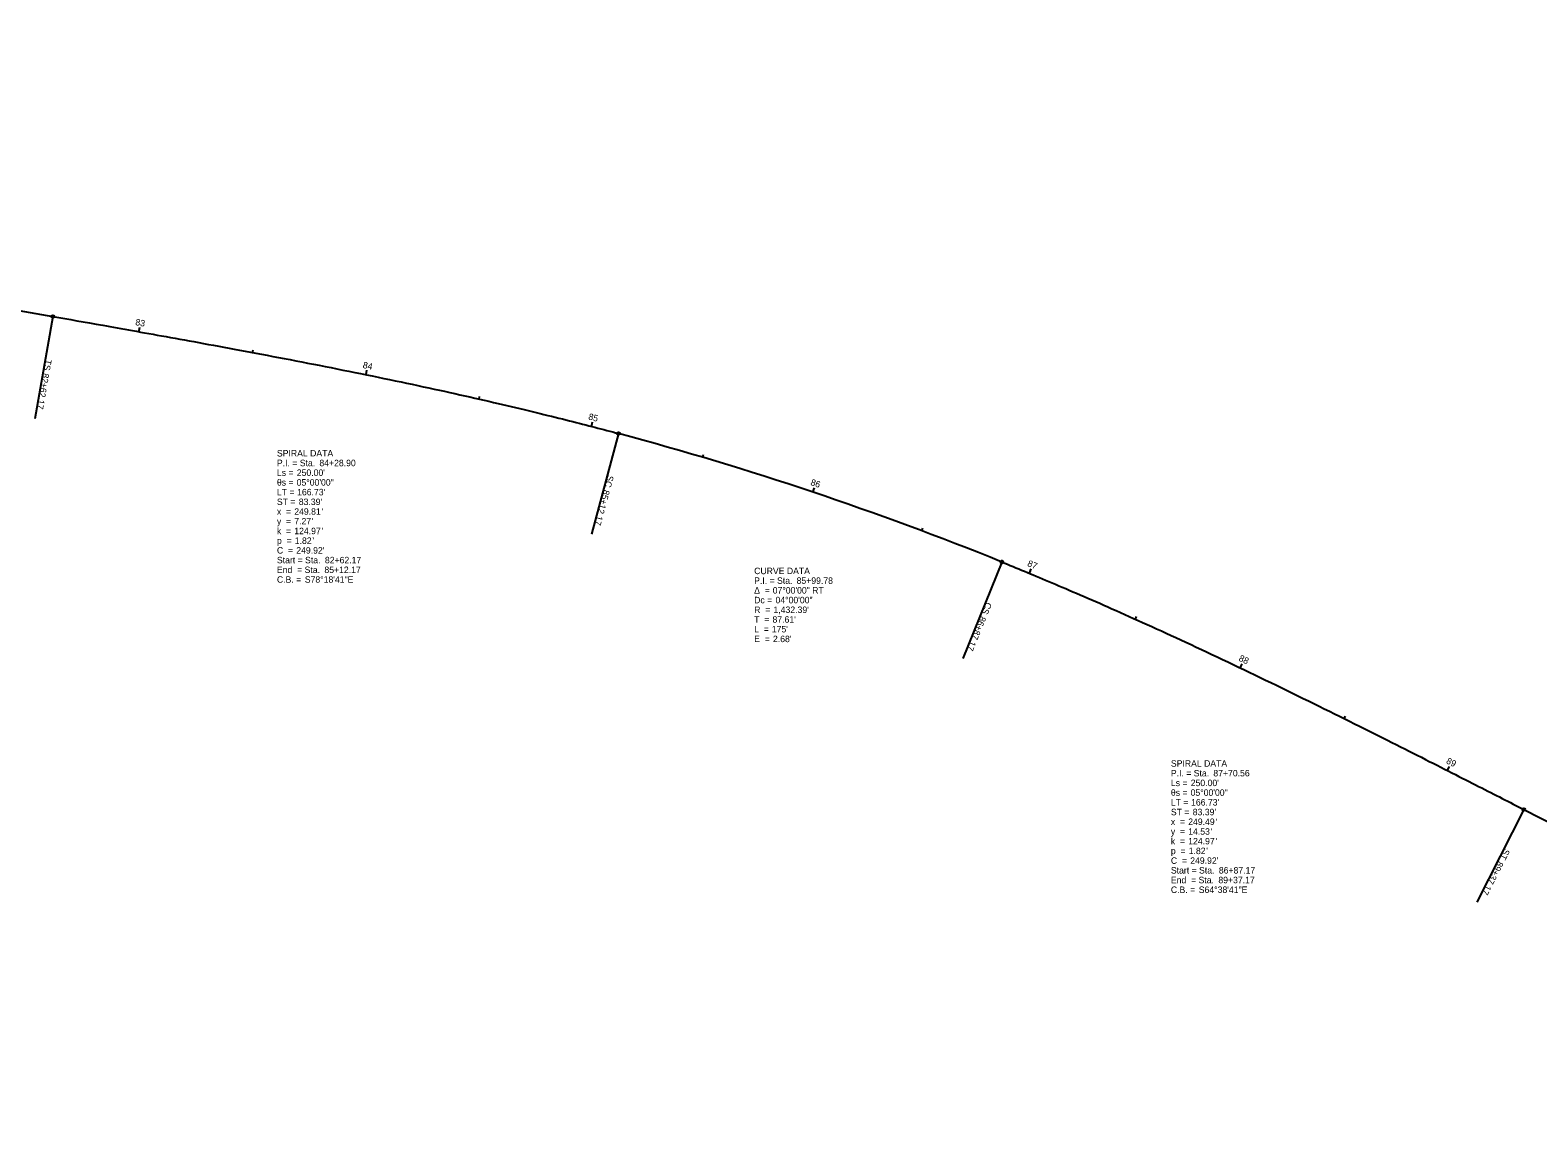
# Model space of a CAD drawing. Extents: x 1999336 to 2003366, y 252766 to 253936.
# Drawn here: x 2000958 to 2001610, y 252978 to 253453 of the extents above; entities that cross this region are included whole.
import ezdxf

# ---------------------------------------------------------------- set-up
doc = ezdxf.new("R2010")
doc.units = 0
for name, color, linetype in [('GE_X_CL_20', 7, 'Continuous'), ('GK_Visualization', 7, 'Continuous'), ('RW_X_Esmt_SH', 7, 'Continuous'), ('SC_Scratch3', 7, 'Continuous'), ('SV_X_Control_Cells_Found', 7, 'Continuous'), ('SV_X_Text_Elevation', 7, 'Continuous'), ('SV_X_Text_Name', 7, 'Continuous')]:
    doc.layers.add(name, color=color, linetype=linetype)

msp = doc.modelspace()

# ---------------------------------------------------------------- linework, layer by layer
at = {"layer": 'GE_X_CL_20'}
for p, q in [((2000967.83, 253329.36), (2000960, 253285.05)), ((2001005.08, 253322.76), (2001005.29, 253323.94)), ((2001103.34, 253304.18), (2001103.58, 253305.36)), ((2001200.8, 253281.84), (2001201.3, 253283.77)), ((2001212.56, 253278.73), (2001200.9, 253235.27)), ((2001296.64, 253253.38), (2001297.02, 253254.52)), ((2001378.39, 253223.18), (2001361.52, 253181.46)), ((2001390.27, 253218.31), (2001390.73, 253219.42)), ((2001481.5, 253177.4), (2001482.02, 253178.48)), ((2001571.11, 253133.02), (2001571.66, 253134.09)), ((2001604.23, 253116.16), (2001583.79, 253076.07))]:
    msp.add_line(p, q, dxfattribs=at)
for centre in [(2000967.83, 253329.36), (2001212.56, 253278.73), (2001378.39, 253223.18), (2001604.23, 253116.16)]:
    msp.add_circle(centre, 0.6, dxfattribs=at)
at = {"layer": 'GK_Visualization'}
for p, q in [((2000267.25, 253453.17), (2000967.83, 253329.36)), ((2001604.23, 253116.16), (2001875.85, 252977.63))]:
    msp.add_line(p, q, dxfattribs=at)
msp.add_arc((2000841.3, 251895.29), 1432.39, 67.97811, 74.97808, dxfattribs=at)
msp.add_arc((2000841.3, 251895.29), 1432.39, 67.97811, 74.97808, dxfattribs=at)
for points in [[(2000967.83, 253329.36), (2000974.67, 253328.16), (2000988.34, 253325.74), (2001015.69, 253320.87), (2001049.85, 253314.66), (2001090.78, 253306.82), (2001131.58, 253298.37), (2001165.44, 253290.68), (2001192.41, 253284.04), (2001205.85, 253280.53), (2001212.56, 253278.73)], [(2000967.83, 253329.36), (2000974.67, 253328.16), (2000988.34, 253325.74), (2001015.69, 253320.87), (2001049.85, 253314.66), (2001090.78, 253306.82), (2001131.58, 253298.37), (2001165.44, 253290.68), (2001192.41, 253284.04), (2001205.85, 253280.53), (2001212.56, 253278.73)], [(2001378.39, 253223.18), (2001384.83, 253220.57), (2001397.67, 253215.27), (2001423.2, 253204.33), (2001454.86, 253190.07), (2001492.51, 253172.23), (2001529.9, 253153.84), (2001560.91, 253138.21), (2001585.67, 253125.62), (2001598.05, 253119.31), (2001604.23, 253116.16)], [(2001378.39, 253223.18), (2001384.83, 253220.57), (2001397.67, 253215.27), (2001423.2, 253204.33), (2001454.86, 253190.07), (2001492.51, 253172.23), (2001529.9, 253153.84), (2001560.91, 253138.21), (2001585.67, 253125.62), (2001598.05, 253119.31), (2001604.23, 253116.16)]]:
    msp.add_open_spline(points, degree=3, dxfattribs=at)
at = {"layer": 'SC_Scratch3'}
for p, q in [((2000967.83, 253329.36), (2000960, 253285.05)), ((2001005.08, 253322.76), (2001005.43, 253324.72)), ((2001054.26, 253313.77), (2001054.49, 253314.95)), ((2001103.34, 253304.18), (2001103.74, 253306.14)), ((2001152.21, 253293.65), (2001152.48, 253294.82)), ((2001200.8, 253281.84), (2001201.3, 253283.77)), ((2001212.56, 253278.73), (2001200.9, 253235.27)), ((2001248.97, 253268.45), (2001249.31, 253269.6)), ((2001296.64, 253253.38), (2001297.28, 253255.28)), ((2001343.76, 253236.66), (2001344.18, 253237.79)), ((2001378.39, 253223.18), (2001361.52, 253181.46)), ((2001390.27, 253218.31), (2001391.03, 253220.16)), ((2001436.15, 253198.45), (2001436.64, 253199.55)), ((2001481.5, 253177.4), (2001482.36, 253179.2)), ((2001526.44, 253155.48), (2001526.98, 253156.56)), ((2001571.11, 253133.02), (2001572.02, 253134.8)), ((2001604.23, 253116.16), (2001583.79, 253076.07))]:
    msp.add_line(p, q, dxfattribs=at)
for centre in [(2000967.83, 253329.36), (2001212.56, 253278.73), (2001378.39, 253223.18), (2001604.23, 253116.16)]:
    msp.add_circle(centre, 0.6, dxfattribs=at)
at = {"layer": 'SV_X_Text_Name'}
for p, q in [((2000967.83, 253329.36), (2000960, 253285.05)), ((2001200.8, 253281.84), (2001201.1, 253283)), ((2001212.56, 253278.73), (2001200.9, 253235.27)), ((2001378.39, 253223.18), (2001361.52, 253181.46)), ((2001604.23, 253116.16), (2001583.79, 253076.07))]:
    msp.add_line(p, q, dxfattribs=at)
for centre in [(2000967.83, 253329.36), (2001212.56, 253278.73), (2001378.39, 253223.18), (2001604.23, 253116.16)]:
    msp.add_circle(centre, 0.6, dxfattribs=at)

# ---------------------------------------------------------------- texts
at = {"layer": 'GE_X_CL_20'}
for s, rotation, p in [('82+62.17', 259.97809, (2000963.57, 253304.98)), ('TS', 259.97809, (2000964.62, 253310.97)), ('85', 345.45294, (2001199.3, 253284.86)), ('SC', 254.97808, (2001207.82, 253260.9)), ('85+12.17', 254.97808, (2001206.13, 253254.6)), ('86+87.17', 247.97811, (2001369.07, 253200.01)), ('CS', 247.97811, (2001371.52, 253206.05)), ('ST', 242.97809, (2001595.79, 253099.5)), ('89+37.17', 242.97809, (2001593.03, 253094.08))]:
    msp.add_text(s, height=2.8, rotation=rotation, dxfattribs=at).set_placement(p)
at = {"layer": 'RW_X_Esmt_SH'}
for s, p in [('SPIRAL DATA', (2001064.78, 253268.81)), ('P.I. = Sta. ', (2001064.78, 253264.61)), ('84+28.90', (2001083.15, 253264.61)), ('θs = ', (2001064.78, 253256.21)), ('Ls = ', (2001064.78, 253260.41)), ('05°00\'00"', (2001073.31, 253256.21)), ("250.00'", (2001073.37, 253260.41)), ('LT = ', (2001064.78, 253252.01)), ("166.73'", (2001073.51, 253252.01)), ('x  = ', (2001064.78, 253243.61)), ('ST = ', (2001064.78, 253247.81)), ('249.81', (2001072.28, 253243.61)), ("83.39'", (2001074.24, 253247.81)), ("'", (2001084.24, 253243.61)), ('y  = ', (2001064.78, 253239.41)), ('7.27', (2001072.28, 253239.41)), ("'", (2001079.89, 253239.41)), ('p  = ', (2001064.78, 253231.01)), ('k  = ', (2001064.78, 253235.21)), ('124.97', (2001072.28, 253235.21)), ('1.82', (2001072.5, 253231.01)), ("'", (2001080.11, 253231.01)), ("'", (2001084.24, 253235.21)), ('C  = ', (2001064.78, 253226.81)), ("249.92'", (2001073.15, 253226.81)), ('Start = Sta. ', (2001064.78, 253222.61)), ('End  = Sta. ', (2001064.78, 253218.41)), ('85+12.17', (2001085.32, 253218.41)), ('82+62.17', (2001085.54, 253222.61)), ('CURVE DATA', (2001271.23, 253217.93)), ('C.B. = ', (2001064.78, 253214.21)), ('S78°18\'41"E', (2001076.84, 253214.21)), ('P.I. = Sta. ', (2001271.23, 253213.73)), ('85+99.78', (2001289.59, 253213.73)), ('Δ  = ', (2001271.23, 253209.53)), ('Dc = ', (2001271.23, 253205.33)), ('07°00\'00" RT', (2001279.25, 253209.53)), ('04°00\'00"', (2001280.46, 253205.33)), ('T  = ', (2001271.23, 253196.93)), ('R  = ', (2001271.23, 253201.13)), ("87.61'", (2001279.16, 253196.93)), ("1,432.39'", (2001279.59, 253201.13)), ('L  = ', (2001271.23, 253192.73)), ("175'", (2001278.87, 253192.73)), ('E  = ', (2001271.23, 253188.53)), ("2.68'", (2001279.38, 253188.53)), ('SPIRAL DATA', (2001451.5, 253134.66)), ('P.I. = Sta. ', (2001451.5, 253130.46)), ('Ls = ', (2001451.5, 253126.26)), ("250.00'", (2001460.09, 253126.26)), ('87+70.56', (2001469.87, 253130.46)), ('θs = ', (2001451.5, 253122.06)), ('05°00\'00"', (2001460.04, 253122.06)), ('ST = ', (2001451.5, 253113.66)), ('LT = ', (2001451.5, 253117.86)), ("166.73'", (2001460.23, 253117.86)), ("83.39'", (2001460.96, 253113.66)), ('x  = ', (2001451.5, 253109.46)), ('249.49', (2001459, 253109.46)), ("'", (2001470.96, 253109.46)), ('y  = ', (2001451.5, 253105.26)), ('k  = ', (2001451.5, 253101.06)), ('14.53', (2001459, 253105.26)), ('124.97', (2001459, 253101.06)), ("'", (2001468.79, 253105.26)), ("'", (2001470.96, 253101.06)), ('C  = ', (2001451.5, 253092.66)), ('p  = ', (2001451.5, 253096.86)), ('1.82', (2001459.22, 253096.86)), ("249.92'", (2001459.87, 253092.66)), ("'", (2001466.83, 253096.86)), ('Start = Sta. ', (2001451.5, 253088.46)), ('86+87.17', (2001472.26, 253088.46)), ('C.B. = ', (2001451.5, 253080.06)), ('End  = Sta. ', (2001451.5, 253084.26)), ('S64°38\'41"E', (2001463.57, 253080.06)), ('89+37.17', (2001472.05, 253084.26))]:
    msp.add_text(s, height=2.8, dxfattribs=at).set_placement(p)
at = {"layer": 'SC_Scratch3'}
for s, rotation, p in [('83', 349.86359, (2001003.38, 253325.65)), ('82+62.17', 259.97809, (2000963.57, 253304.98)), ('TS', 259.97809, (2000964.62, 253310.97)), ('84', 348.45827, (2001101.74, 253307.11)), ('85', 345.45294, (2001199.3, 253284.86)), ('SC', 254.97808, (2001207.82, 253260.9)), ('86', 341.46477, (2001295.37, 253256.5)), ('85+12.17', 254.97808, (2001206.13, 253254.6)), ('87', 337.47794, (2001389.16, 253221.53)), ('86+87.17', 247.97811, (2001369.07, 253200.01)), ('CS', 247.97811, (2001371.52, 253206.05)), ('88', 334.48327, (2001480.62, 253180.64)), ('89', 333.0886, (2001570.33, 253136.27)), ('ST', 242.97809, (2001595.79, 253099.5)), ('89+37.17', 242.97809, (2001593.03, 253094.08))]:
    msp.add_text(s, height=2.8, rotation=rotation, dxfattribs=at).set_placement(p)
at = {"layer": 'SV_X_Control_Cells_Found'}
for s, p in [('SPIRAL DATA', (2001064.78, 253268.81)), ('P.I. = Sta. ', (2001064.78, 253264.61)), ('84+28.90', (2001083.15, 253264.61)), ('θs = ', (2001064.78, 253256.21)), ('Ls = ', (2001064.78, 253260.41)), ('05°00\'00"', (2001073.31, 253256.21)), ("250.00'", (2001073.37, 253260.41)), ('LT = ', (2001064.78, 253252.01)), ("166.73'", (2001073.51, 253252.01)), ('x  = ', (2001064.78, 253243.61)), ('ST = ', (2001064.78, 253247.81)), ('249.81', (2001072.28, 253243.61)), ("83.39'", (2001074.24, 253247.81)), ("'", (2001084.24, 253243.61)), ('y  = ', (2001064.78, 253239.41)), ('7.27', (2001072.28, 253239.41)), ("'", (2001079.89, 253239.41)), ('p  = ', (2001064.78, 253231.01)), ('k  = ', (2001064.78, 253235.21)), ('124.97', (2001072.28, 253235.21)), ('1.82', (2001072.5, 253231.01)), ("'", (2001080.11, 253231.01)), ("'", (2001084.24, 253235.21)), ('C  = ', (2001064.78, 253226.81)), ("249.92'", (2001073.15, 253226.81)), ('Start = Sta. ', (2001064.78, 253222.61)), ('End  = Sta. ', (2001064.78, 253218.41)), ('85+12.17', (2001085.32, 253218.41)), ('82+62.17', (2001085.54, 253222.61)), ('CURVE DATA', (2001271.23, 253217.93)), ('C.B. = ', (2001064.78, 253214.21)), ('S78°18\'41"E', (2001076.84, 253214.21)), ('P.I. = Sta. ', (2001271.23, 253213.73)), ('85+99.78', (2001289.59, 253213.73)), ('Δ  = ', (2001271.23, 253209.53)), ('Dc = ', (2001271.23, 253205.33)), ('07°00\'00" RT', (2001279.25, 253209.53)), ('04°00\'00"', (2001280.46, 253205.33)), ('T  = ', (2001271.23, 253196.93)), ('R  = ', (2001271.23, 253201.13)), ("87.61'", (2001279.16, 253196.93)), ("1,432.39'", (2001279.59, 253201.13)), ('L  = ', (2001271.23, 253192.73)), ("175'", (2001278.87, 253192.73)), ('E  = ', (2001271.23, 253188.53)), ("2.68'", (2001279.38, 253188.53)), ('SPIRAL DATA', (2001451.5, 253134.66)), ('P.I. = Sta. ', (2001451.5, 253130.46)), ('Ls = ', (2001451.5, 253126.26)), ("250.00'", (2001460.09, 253126.26)), ('87+70.56', (2001469.87, 253130.46)), ('θs = ', (2001451.5, 253122.06)), ('05°00\'00"', (2001460.04, 253122.06)), ('ST = ', (2001451.5, 253113.66)), ('LT = ', (2001451.5, 253117.86)), ("166.73'", (2001460.23, 253117.86)), ("83.39'", (2001460.96, 253113.66)), ('x  = ', (2001451.5, 253109.46)), ('249.49', (2001459, 253109.46)), ("'", (2001470.96, 253109.46)), ('y  = ', (2001451.5, 253105.26)), ('k  = ', (2001451.5, 253101.06)), ('14.53', (2001459, 253105.26)), ('124.97', (2001459, 253101.06)), ("'", (2001468.79, 253105.26)), ("'", (2001470.96, 253101.06)), ('C  = ', (2001451.5, 253092.66)), ('p  = ', (2001451.5, 253096.86)), ('1.82', (2001459.22, 253096.86)), ("249.92'", (2001459.87, 253092.66)), ("'", (2001466.83, 253096.86)), ('Start = Sta. ', (2001451.5, 253088.46)), ('86+87.17', (2001472.26, 253088.46)), ('C.B. = ', (2001451.5, 253080.06)), ('End  = Sta. ', (2001451.5, 253084.26)), ('S64°38\'41"E', (2001463.57, 253080.06)), ('89+37.17', (2001472.05, 253084.26))]:
    msp.add_text(s, height=2.8, dxfattribs=at).set_placement(p)
at = {"layer": 'SV_X_Text_Elevation'}
for s, p in [('SPIRAL DATA', (2001064.78, 253268.81)), ('P.I. = Sta. ', (2001064.78, 253264.61)), ('84+28.90', (2001083.15, 253264.61)), ('θs = ', (2001064.78, 253256.21)), ('Ls = ', (2001064.78, 253260.41)), ('05°00\'00"', (2001073.31, 253256.21)), ("250.00'", (2001073.37, 253260.41)), ('LT = ', (2001064.78, 253252.01)), ("166.73'", (2001073.51, 253252.01)), ('x  = ', (2001064.78, 253243.61)), ('ST = ', (2001064.78, 253247.81)), ('249.81', (2001072.28, 253243.61)), ("83.39'", (2001074.24, 253247.81)), ("'", (2001084.24, 253243.61)), ('y  = ', (2001064.78, 253239.41)), ('7.27', (2001072.28, 253239.41)), ("'", (2001079.89, 253239.41)), ('p  = ', (2001064.78, 253231.01)), ('k  = ', (2001064.78, 253235.21)), ('124.97', (2001072.28, 253235.21)), ('1.82', (2001072.5, 253231.01)), ("'", (2001080.11, 253231.01)), ("'", (2001084.24, 253235.21)), ('C  = ', (2001064.78, 253226.81)), ("249.92'", (2001073.15, 253226.81)), ('Start = Sta. ', (2001064.78, 253222.61)), ('End  = Sta. ', (2001064.78, 253218.41)), ('85+12.17', (2001085.32, 253218.41)), ('82+62.17', (2001085.54, 253222.61)), ('CURVE DATA', (2001271.23, 253217.93)), ('C.B. = ', (2001064.78, 253214.21)), ('S78°18\'41"E', (2001076.84, 253214.21)), ('P.I. = Sta. ', (2001271.23, 253213.73)), ('85+99.78', (2001289.59, 253213.73)), ('Δ  = ', (2001271.23, 253209.53)), ('Dc = ', (2001271.23, 253205.33)), ('07°00\'00" RT', (2001279.25, 253209.53)), ('04°00\'00"', (2001280.46, 253205.33)), ('T  = ', (2001271.23, 253196.93)), ('R  = ', (2001271.23, 253201.13)), ("87.61'", (2001279.16, 253196.93)), ("1,432.39'", (2001279.59, 253201.13)), ('L  = ', (2001271.23, 253192.73)), ("175'", (2001278.87, 253192.73)), ('E  = ', (2001271.23, 253188.53)), ("2.68'", (2001279.38, 253188.53)), ('SPIRAL DATA', (2001451.5, 253134.66)), ('P.I. = Sta. ', (2001451.5, 253130.46)), ('Ls = ', (2001451.5, 253126.26)), ("250.00'", (2001460.09, 253126.26)), ('87+70.56', (2001469.87, 253130.46)), ('θs = ', (2001451.5, 253122.06)), ('05°00\'00"', (2001460.04, 253122.06)), ('ST = ', (2001451.5, 253113.66)), ('LT = ', (2001451.5, 253117.86)), ("166.73'", (2001460.23, 253117.86)), ("83.39'", (2001460.96, 253113.66)), ('x  = ', (2001451.5, 253109.46)), ('249.49', (2001459, 253109.46)), ("'", (2001470.96, 253109.46)), ('y  = ', (2001451.5, 253105.26)), ('k  = ', (2001451.5, 253101.06)), ('14.53', (2001459, 253105.26)), ('124.97', (2001459, 253101.06)), ("'", (2001468.79, 253105.26)), ("'", (2001470.96, 253101.06)), ('C  = ', (2001451.5, 253092.66)), ('p  = ', (2001451.5, 253096.86)), ('1.82', (2001459.22, 253096.86)), ("249.92'", (2001459.87, 253092.66)), ("'", (2001466.83, 253096.86)), ('Start = Sta. ', (2001451.5, 253088.46)), ('86+87.17', (2001472.26, 253088.46)), ('C.B. = ', (2001451.5, 253080.06)), ('End  = Sta. ', (2001451.5, 253084.26)), ('S64°38\'41"E', (2001463.57, 253080.06)), ('89+37.17', (2001472.05, 253084.26))]:
    msp.add_text(s, height=2.8, dxfattribs=at).set_placement(p)
at = {"layer": 'SV_X_Text_Name'}
for s, rotation, p in [('82+62.17', 259.97809, (2000963.57, 253304.98)), ('TS', 259.97809, (2000964.62, 253310.97)), ('SC', 254.97808, (2001207.82, 253260.9)), ('85+12.17', 254.97808, (2001206.13, 253254.6)), ('86+87.17', 247.97811, (2001369.07, 253200.01)), ('CS', 247.97811, (2001371.52, 253206.05)), ('ST', 242.97809, (2001595.79, 253099.5)), ('89+37.17', 242.97809, (2001593.03, 253094.08))]:
    msp.add_text(s, height=2.8, rotation=rotation, dxfattribs=at).set_placement(p)

doc.saveas('drawing.dxf')
